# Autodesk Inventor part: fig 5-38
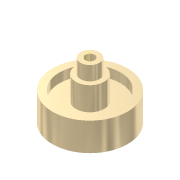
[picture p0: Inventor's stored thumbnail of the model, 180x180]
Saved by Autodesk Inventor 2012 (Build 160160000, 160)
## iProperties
Shininess: 65.0
Length Units: 11269
Angle Units: 11279
Time Units: 11290
Mass Units: 11283
Length Display Precision: 3
Angle Display Precision: 2
Created: 2001-11
Part Number: fig 5-38
Document SubType Name: Modeling
Designer: Renu Muthoo
Density: 1 g/cm^3
Material: Default
Density: 0.0
Volumn: 0.0
Area: 0.0
PropertySet Name: Model Information
Control State: 0
Master: False
Checked Out: False
Author: Renu Muthoo
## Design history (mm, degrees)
sketch "Sketch1"
  geometry: L1 (2.694, 30.112)-(5.194, 30.112); L2 (5.194, 30.112)-(5.194, 22.612); L3 (5.194, 22.612)-(7.694, 22.612); L4 (7.694, 22.612)-(7.694, 10.112); L5 (7.694, 10.112)-(16.444, 10.112); L6 (16.444, 10.112)-(16.444, 15.112); L7 (16.444, 15.112)-(20.194, 15.112); L8 (0.194, -4.034)-(0.194, 25.966); L9 (2.694, 30.112)-(2.694, 0.112); L10 (2.694, 0.112)-(20.194, 0.112); L11 (20.194, 0.112)-(20.194, 15.112)
  constraints: 22 end point, 7 parallel, 2 perpendicular, 1 horizontal
  dimensions: "d0" = 5 diameter of L9 L8; "d1" = 10 diameter of L2 L8; "d2" = 15 diameter of L4 L8; "d3" = 32.5 diameter of L6 L8; "d4" = 40 diameter of L11 L8; "d5" = 15 distance of L10.end L7.end; "d6" = 22.5 distance between parallel lines of L3 L10; "d7" = 30 distance between parallel lines of L1 L10; "d8" = 10 distance between parallel lines of L10 L5
revolve "Revolution1" sketch "Sketch1" stored, may be unused: angle "d9" = 90 deg
workaxis "Work Axis1"
node "Sketch3"
workaxis "Work Axis4"
body "Solid1"
